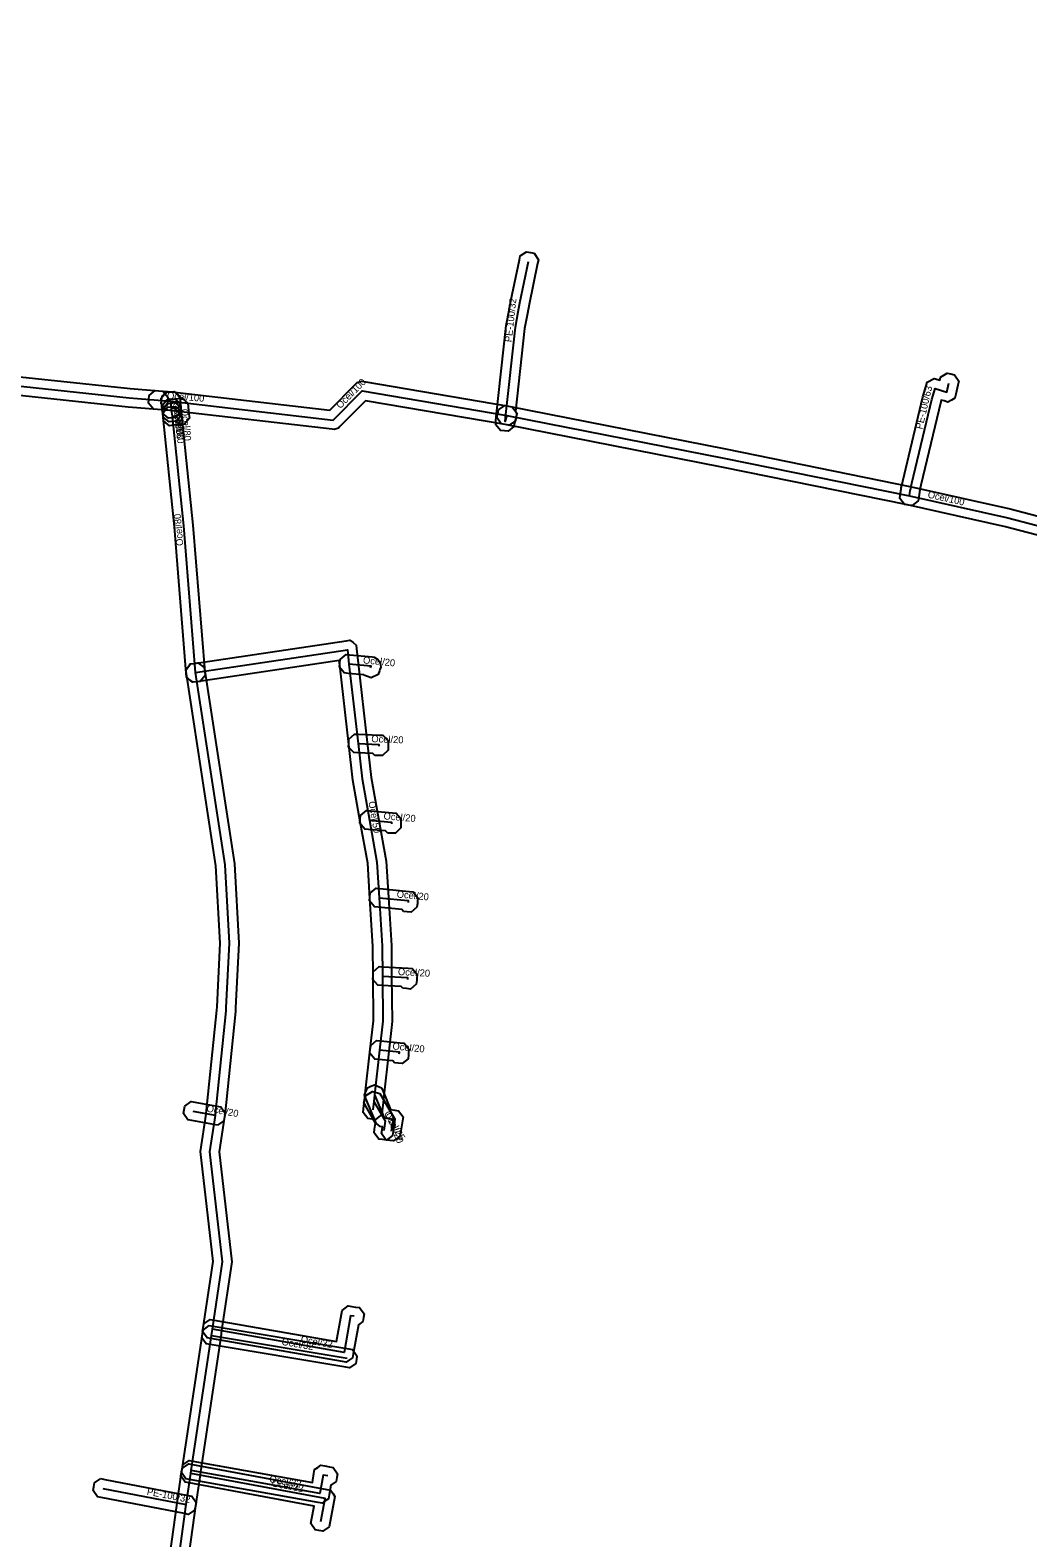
# Model space of a CAD drawing. Extents: x -569373 to -565022, y -1135090 to -1131496.
# Drawn here: x -566386.5 to -566279.2, y -1133844.4 to -1133682.3 of the extents above; entities that cross this region are included whole.
import ezdxf

# ---------------------------------------------------------------- set-up
doc = ezdxf.new("R2010")
doc.units = 0
for name, color, linetype in [('1', 7, 'Continuous'), ('24', 7, 'Continuous'), ('30', 7, 'Continuous')]:
    doc.layers.add(name, color=color, linetype=linetype)

msp = doc.modelspace()

# ---------------------------------------------------------------- linework, layer by layer
at = {"layer": '1'}
for points in [[(-566334.378, -1133724.484), (-566334.378, -1133724.487), (-566334.428, -1133724.884), (-566335.054, -1133725.391), (-566335.456, -1133725.356), (-566335.858, -1133725.322), (-566336.388, -1133724.715), (-566336.369, -1133724.312), (-566336.347, -1133723.861), (-566335.26, -1133714.052), (-566334.947, -1133712.384), (-566334.761, -1133711.396), (-566333.839, -1133706.966), (-566333.755, -1133706.56), (-566333.062, -1133706.107), (-566332.656, -1133706.191), (-566332.25, -1133706.275), (-566331.797, -1133706.968), (-566331.881, -1133707.374), (-566332.799, -1133711.784), (-566332.981, -1133712.754), (-566333.28, -1133714.348), (-566334.273, -1133723.294), (-566334.114, -1133723.584), (-566334.23, -1133723.981)], [(-566288.851, -1133719.853), (-566288.618, -1133719.923), (-566288.543, -1133719.595), (-566287.843, -1133719.153), (-566287.439, -1133719.245), (-566287.035, -1133719.337), (-566286.593, -1133720.037), (-566286.685, -1133720.441), (-566286.905, -1133721.411), (-566287.001, -1133721.835), (-566287.377, -1133722.054), (-566287.752, -1133722.273), (-566288.169, -1133722.147), (-566288.477, -1133722.055), (-566288.534, -1133722.242), (-566290.656, -1133731.215), (-566290.724, -1133731.52), (-566290.814, -1133731.918), (-566290.824, -1133731.961), (-566290.888, -1133732.474), (-566290.939, -1133732.885), (-566291.593, -1133733.393), (-566292.004, -1133733.342), (-566292.415, -1133733.291), (-566292.923, -1133732.637), (-566292.872, -1133732.226), (-566292.796, -1133731.619), (-566292.766, -1133731.482), (-566292.676, -1133731.08), (-566292.604, -1133730.765), (-566290.466, -1133721.718), (-566290.096, -1133720.516), (-566289.974, -1133720.121), (-566289.246, -1133719.734)], [(-566371.626, -1133721.129), (-566371.215, -1133721.177), (-566354.229, -1133723.15), (-566351.462, -1133720.347), (-566351.29, -1133720.173), (-566350.824, -1133720.023), (-566350.582, -1133720.064), (-566335.022, -1133722.714), (-566334.614, -1133722.784), (-566334.134, -1133723.46), (-566334.204, -1133723.868), (-566334.274, -1133724.276), (-566334.95, -1133724.756), (-566335.358, -1133724.686), (-566350.404, -1133722.123), (-566353.148, -1133724.903), (-566353.31, -1133725.067), (-566353.746, -1133725.22), (-566353.975, -1133725.193), (-566371.445, -1133723.163), (-566371.857, -1133723.115), (-566372.371, -1133722.466), (-566372.323, -1133722.055), (-566372.275, -1133721.643)], [(-566373.022, -1133721.03), (-566372.609, -1133721.063), (-566371.249, -1133721.173), (-566370.836, -1133721.207), (-566370.3, -1133721.838), (-566370.333, -1133722.251), (-566370.367, -1133722.664), (-566370.998, -1133723.2), (-566371.411, -1133723.167), (-566372.771, -1133723.057), (-566373.184, -1133723.023), (-566373.72, -1133722.392), (-566373.687, -1133721.979), (-566373.653, -1133721.566)], [(-566372.204, -1133723.482), (-566372.245, -1133723.07), (-566372.325, -1133722.27), (-566372.366, -1133721.857), (-566371.842, -1133721.216), (-566371.43, -1133721.175), (-566371.017, -1133721.134), (-566370.376, -1133721.658), (-566370.335, -1133722.07), (-566370.255, -1133722.87), (-566370.214, -1133723.283), (-566370.738, -1133723.924), (-566371.15, -1133723.965), (-566371.563, -1133724.006)], [(-566372.153, -1133723.894), (-566372.199, -1133723.482), (-566372.244, -1133723.082), (-566372.29, -1133722.67), (-566371.774, -1133722.022), (-566371.362, -1133721.976), (-566370.95, -1133721.93), (-566370.302, -1133722.446), (-566370.256, -1133722.858), (-566370.211, -1133723.258), (-566370.165, -1133723.67), (-566370.681, -1133724.318), (-566371.093, -1133724.364), (-566371.505, -1133724.41)], [(-566372.154, -1133723.883), (-566372.2, -1133723.484), (-566372.205, -1133723.48), (-566372.245, -1133723.068), (-566372.286, -1133722.655), (-566371.76, -1133722.015), (-566371.348, -1133721.975), (-566370.84, -1133721.925), (-566370.553, -1133721.895), (-566370.14, -1133721.853), (-566369.819, -1133722.115), (-566369.497, -1133722.377), (-566369.455, -1133722.789), (-566369.375, -1133723.579), (-566369.334, -1133723.988), (-566369.849, -1133724.627), (-566370.257, -1133724.674), (-566371.047, -1133724.764), (-566371.458, -1133724.811), (-566372.107, -1133724.295)], [(-566372.108, -1133724.294), (-566372.154, -1133723.882), (-566372.199, -1133723.482), (-566372.245, -1133723.07), (-566371.729, -1133722.422), (-566371.317, -1133722.376), (-566370.905, -1133722.33), (-566370.257, -1133722.846), (-566370.211, -1133723.258), (-566370.166, -1133723.658), (-566370.12, -1133724.07), (-566370.636, -1133724.718), (-566371.048, -1133724.764), (-566371.46, -1133724.81)], [(-566369.633, -1133751.843), (-566369.667, -1133751.43), (-566370.936, -1133735.682), (-566372.155, -1133723.873), (-566372.197, -1133723.461), (-566371.675, -1133722.818), (-566371.263, -1133722.775), (-566370.851, -1133722.733), (-566370.208, -1133723.255), (-566370.165, -1133723.667), (-566368.944, -1133735.498), (-566367.673, -1133751.27), (-566367.64, -1133751.683), (-566368.177, -1133752.313), (-566368.59, -1133752.347), (-566369.003, -1133752.38)], [(-566335.403, -1133722.639), (-566334.997, -1133722.719), (-566311.664, -1133727.309), (-566291.671, -1133731.372), (-566281.074, -1133733.748), (-566267.252, -1133737.363), (-566262.727, -1133738.207), (-566245.247, -1133741.457), (-566244.84, -1133741.533), (-566244.371, -1133742.216), (-566244.447, -1133742.623), (-566244.523, -1133743.03), (-566245.206, -1133743.499), (-566245.613, -1133743.423), (-566263.093, -1133740.173), (-566267.688, -1133739.317), (-566281.546, -1133735.692), (-566292.089, -1133733.328), (-566312.056, -1133729.271), (-566335.383, -1133724.681), (-566335.789, -1133724.601), (-566336.251, -1133723.913), (-566336.171, -1133723.507), (-566336.091, -1133723.101)], [(-566369.227, -1133750.422), (-566368.817, -1133750.361), (-566352.487, -1133747.931), (-566352.067, -1133747.868), (-566351.73, -1133748.127), (-566351.393, -1133748.387), (-566351.346, -1133748.809), (-566351.176, -1133750.327), (-566350.196, -1133758.866), (-566349.77, -1133762.616), (-566348.986, -1133767.045), (-566348.165, -1133771.622), (-566347.932, -1133775.519), (-566347.61, -1133780.704), (-566347.58, -1133783.98), (-566347.529, -1133788.881), (-566347.886, -1133792.062), (-566348.426, -1133796.872), (-566348.506, -1133797.582), (-566348.606, -1133798.472), (-566348.652, -1133798.883), (-566349.3, -1133799.4), (-566349.712, -1133799.354), (-566350.123, -1133799.308), (-566350.64, -1133798.66), (-566350.594, -1133798.248), (-566350.494, -1133797.358), (-566350.414, -1133796.648), (-566349.874, -1133791.838), (-566349.531, -1133788.779), (-566349.58, -1133784), (-566349.61, -1133780.776), (-566349.928, -1133775.641), (-566350.155, -1133771.858), (-566350.954, -1133767.395), (-566351.75, -1133762.904), (-566352.184, -1133759.094), (-566353.164, -1133750.553), (-566353.219, -1133750.062), (-566368.523, -1133752.339), (-566368.933, -1133752.4), (-566369.598, -1133751.907), (-566369.659, -1133751.497), (-566369.72, -1133751.087)], [(-566350.564, -1133751.645), (-566350.587, -1133751.597), (-566352.266, -1133751.435), (-566352.678, -1133751.396), (-566353.205, -1133750.757), (-566353.165, -1133750.344), (-566353.126, -1133749.932), (-566352.487, -1133749.405), (-566352.074, -1133749.445), (-566349.684, -1133749.675), (-566349.454, -1133749.697), (-566349.061, -1133749.937), (-566348.937, -1133750.132), (-566348.813, -1133750.327), (-566348.76, -1133750.785), (-566348.837, -1133751.003), (-566348.897, -1133751.173), (-566349.035, -1133751.564), (-566349.782, -1133751.921), (-566350.173, -1133751.783)], [(-566349.374, -1133760.27), (-566349.599, -1133760.045), (-566351.23, -1133759.979), (-566351.644, -1133759.962), (-566352.206, -1133759.354), (-566352.189, -1133758.94), (-566352.172, -1133758.526), (-566351.564, -1133757.964), (-566351.15, -1133757.981), (-566348.92, -1133758.071), (-566348.518, -1133758.087), (-566347.96, -1133758.668), (-566347.96, -1133759.07), (-566347.96, -1133759.27), (-566347.96, -1133759.684), (-566348.546, -1133760.27), (-566348.96, -1133760.27)], [(-566347.994, -1133768.62), (-566348.246, -1133768.368), (-566350.053, -1133768.217), (-566350.466, -1133768.182), (-566351.001, -1133767.55), (-566350.967, -1133767.137), (-566350.932, -1133766.724), (-566350.3, -1133766.189), (-566349.887, -1133766.223), (-566347.497, -1133766.423), (-566347.108, -1133766.456), (-566346.58, -1133767.03), (-566346.58, -1133767.42), (-566346.58, -1133767.62), (-566346.58, -1133768.034), (-566347.166, -1133768.62), (-566347.58, -1133768.62)], [(-566346.322, -1133777.024), (-566346.498, -1133776.809), (-566349.022, -1133776.576), (-566349.435, -1133776.538), (-566349.964, -1133775.901), (-566349.926, -1133775.488), (-566349.888, -1133775.075), (-566349.251, -1133774.546), (-566348.838, -1133774.584), (-566345.698, -1133774.874), (-566345.283, -1133774.913), (-566345.018, -1133775.234), (-566344.754, -1133775.555), (-566344.795, -1133775.97), (-566344.815, -1133776.17), (-566344.856, -1133776.582), (-566345.497, -1133777.106), (-566345.91, -1133777.065)], [(-566346.392, -1133785.294), (-566346.548, -1133785.103), (-566348.635, -1133784.988), (-566349.049, -1133784.965), (-566349.601, -1133784.348), (-566349.578, -1133783.935), (-566349.555, -1133783.521), (-566348.938, -1133782.969), (-566348.525, -1133782.992), (-566345.805, -1133783.142), (-566345.378, -1133783.165), (-566345.1, -1133783.49), (-566344.822, -1133783.814), (-566344.865, -1133784.24), (-566344.885, -1133784.44), (-566344.926, -1133784.852), (-566345.567, -1133785.376), (-566345.98, -1133785.335)], [(-566347.282, -1133793.314), (-566347.461, -1133793.095), (-566348.978, -1133792.945), (-566349.39, -1133792.904), (-566349.916, -1133792.264), (-566349.875, -1133791.852), (-566349.834, -1133791.44), (-566349.194, -1133790.914), (-566348.782, -1133790.955), (-566346.652, -1133791.165), (-566346.239, -1133791.206), (-566345.976, -1133791.526), (-566345.714, -1133791.847), (-566345.755, -1133792.26), (-566345.775, -1133792.46), (-566345.816, -1133792.872), (-566346.457, -1133793.396), (-566346.87, -1133793.355)], [(-566348.842, -1133796.611), (-566348.634, -1133796.969), (-566347.242, -1133799.378), (-566347.43, -1133800.71), (-566347.488, -1133801.12), (-566348.15, -1133801.618), (-566348.56, -1133801.56), (-566348.97, -1133801.502), (-566349.468, -1133800.84), (-566349.41, -1133800.43), (-566349.318, -1133799.782), (-566350.366, -1133797.971), (-566350.573, -1133797.612), (-566350.359, -1133796.812), (-566350.001, -1133796.604), (-566349.642, -1133796.397)], [(-566348.655, -1133795.994), (-566348.496, -1133796.377), (-566347.69, -1133798.322), (-566347.25, -1133798.393), (-566346.841, -1133798.459), (-566346.598, -1133798.796), (-566346.356, -1133799.132), (-566346.423, -1133799.542), (-566346.633, -1133800.822), (-566346.7, -1133801.231), (-566347.373, -1133801.714), (-566347.782, -1133801.647), (-566348.191, -1133801.58), (-566348.674, -1133800.907), (-566348.607, -1133800.498), (-566348.559, -1133800.207), (-566348.56, -1133800.207), (-566348.816, -1133800.166), (-566349.224, -1133799.843), (-566349.324, -1133799.603), (-566350.344, -1133797.143), (-566350.503, -1133796.76), (-566350.186, -1133795.995), (-566349.803, -1133795.836), (-566349.42, -1133795.677)], [(-566366.306, -1133800.017), (-566366.714, -1133799.945), (-566369.084, -1133799.525), (-566369.492, -1133799.453), (-566369.967, -1133798.774), (-566369.895, -1133798.366), (-566369.823, -1133797.958), (-566369.144, -1133797.483), (-566368.736, -1133797.555), (-566366.366, -1133797.975), (-566365.958, -1133798.047), (-566365.483, -1133798.726), (-566365.555, -1133799.134), (-566365.627, -1133799.542)], [(-566350.672, -1133821.118), (-566351.155, -1133821.475), (-566351.705, -1133824.613), (-566351.776, -1133825.021), (-566352.116, -1133825.259), (-566352.455, -1133825.497), (-566352.863, -1133825.425), (-566367.023, -1133822.935), (-566367.431, -1133822.863), (-566367.907, -1133822.185), (-566367.835, -1133821.777), (-566367.763, -1133821.369), (-566367.085, -1133820.893), (-566366.677, -1133820.965), (-566353.502, -1133823.282), (-566352.985, -1133820.327), (-566352.915, -1133819.926), (-566352.255, -1133819.451), (-566351.852, -1133819.511), (-566351.452, -1133819.571), (-566351.042, -1133819.632), (-566350.55, -1133820.298), (-566350.611, -1133820.708)], [(-566367.194, -1133821.566), (-566366.786, -1133821.634), (-566352.196, -1133824.064), (-566351.787, -1133824.132), (-566351.306, -1133824.806), (-566351.374, -1133825.214), (-566351.442, -1133825.623), (-566352.116, -1133826.104), (-566352.524, -1133826.036), (-566367.114, -1133823.606), (-566367.523, -1133823.538), (-566368.004, -1133822.864), (-566367.936, -1133822.456), (-566367.868, -1133822.047)], [(-566356.27, -1133842.839), (-566356.192, -1133842.432), (-566355.911, -1133840.96), (-566369.362, -1133838.463), (-566369.77, -1133838.388), (-566370.239, -1133837.705), (-566370.163, -1133837.298), (-566370.088, -1133836.89), (-566369.405, -1133836.421), (-566368.998, -1133836.497), (-566354.558, -1133839.177), (-566354.149, -1133839.253), (-566353.914, -1133839.596), (-566353.68, -1133839.939), (-566353.758, -1133840.348), (-566354.228, -1133842.808), (-566354.305, -1133843.215), (-566354.991, -1133843.68), (-566355.398, -1133843.602), (-566355.805, -1133843.525)], [(-566353.551, -1133838.308), (-566354.125, -1133838.704), (-566354.315, -1133839.775), (-566354.388, -1133840.183), (-566354.728, -1133840.42), (-566355.068, -1133840.657), (-566355.476, -1133840.584), (-566369.306, -1133838.114), (-566369.714, -1133838.042), (-566370.187, -1133837.362), (-566370.114, -1133836.954), (-566370.042, -1133836.546), (-566369.362, -1133836.073), (-566368.954, -1133836.146), (-566356.109, -1133838.44), (-566355.935, -1133837.455), (-566355.862, -1133837.046), (-566355.52, -1133836.808), (-566355.178, -1133836.571), (-566354.769, -1133836.646), (-566354.279, -1133836.736), (-566353.872, -1133836.811), (-566353.401, -1133837.493), (-566353.476, -1133837.901)], [(-566378.848, -1133838.02), (-566378.441, -1133838.098), (-566369.481, -1133839.818), (-566369.074, -1133839.896), (-566368.61, -1133840.582), (-566368.688, -1133840.989), (-566368.766, -1133841.396), (-566369.452, -1133841.86), (-566369.859, -1133841.782), (-566378.819, -1133840.062), (-566379.226, -1133839.984), (-566379.69, -1133839.298), (-566379.612, -1133838.891), (-566379.534, -1133838.484)]]:
    msp.add_lwpolyline(points, close=True, dxfattribs=at)
for points in [[(-566396.09, -1133718.644), (-566375.718, -1133720.824), (-566374.824, -1133720.893), (-566372.613, -1133721.063), (-566372.2, -1133721.095), (-566371.661, -1133721.724), (-566371.693, -1133722.137), (-566371.725, -1133722.55), (-566372.354, -1133723.089), (-566372.767, -1133723.057), (-566374.978, -1133722.887), (-566375.902, -1133722.816), (-566396.27, -1133720.636)], [(-566372.717, -1133855.594), (-566370.66, -1133840.659), (-566370.17, -1133837.336), (-566370.119, -1133836.985), (-566367.939, -1133822.472), (-566367.839, -1133821.803), (-566366.779, -1133814.683), (-566368.139, -1133802.852), (-566367.532, -1133798.83), (-566367.524, -1133798.764), (-566366.378, -1133787.635), (-566366.362, -1133787.304), (-566366.031, -1133780.433), (-566366.486, -1133772.124), (-566369.658, -1133751.502), (-566369.721, -1133751.093), (-566369.231, -1133750.425), (-566368.822, -1133750.362), (-566368.413, -1133750.299), (-566367.745, -1133750.789), (-566367.682, -1133751.198), (-566364.494, -1133771.916), (-566364.029, -1133780.427), (-566364.364, -1133787.4), (-566364.382, -1133787.785), (-566365.536, -1133798.976), (-566365.548, -1133799.09), (-566366.121, -1133802.888), (-566364.761, -1133814.717), (-566365.861, -1133822.097), (-566365.961, -1133822.768), (-566368.141, -1133837.275), (-566368.19, -1133837.624), (-566368.68, -1133840.941), (-566370.743, -1133855.926)]]:
    msp.add_lwpolyline(points, dxfattribs=at)
at = {"layer": '24'}
for points in [[(-566655.56, -1133682.28), (-566611.27, -1133691.4), (-566563.79, -1133701.13), (-566514.74, -1133710.21), (-566508.02, -1133711.52), (-566449.74, -1133715.73), (-566419.47, -1133717.94), (-566396.18, -1133719.64), (-566375.81, -1133721.82), (-566374.901, -1133721.89), (-566372.69, -1133722.06)], [(-566335.19, -1133723.7), (-566335.36, -1133724.28), (-566335.37, -1133724.36), (-566335.35, -1133723.94), (-566334.27, -1133714.2), (-566333.964, -1133712.569), (-566333.78, -1133711.59), (-566332.86, -1133707.17)], [(-566291.88, -1133732.35), (-566291.81, -1133731.79), (-566291.79, -1133731.7), (-566291.7, -1133731.3), (-566291.63, -1133730.99), (-566289.5, -1133721.98), (-566289.14, -1133720.81), (-566287.88, -1133721.19), (-566287.66, -1133720.22)], [(-566372.69, -1133722.06), (-566371.33, -1133722.17)], [(-566371.33, -1133722.17), (-566353.86, -1133724.2), (-566350.75, -1133721.05), (-566335.19, -1133723.7)], [(-566371.25, -1133722.97), (-566371.33, -1133722.17)], [(-566371.16, -1133723.77), (-566370.37, -1133723.68), (-566370.45, -1133722.89), (-566370.74, -1133722.92), (-566371.25, -1133722.97)], [(-566371.205, -1133723.37), (-566371.25, -1133722.97)], [(-566371.16, -1133723.77), (-566371.205, -1133723.37)], [(-566368.67, -1133751.35), (-566369.94, -1133735.59), (-566371.16, -1133723.77)], [(-566335.19, -1133723.7), (-566311.86, -1133728.29), (-566291.88, -1133732.35), (-566281.31, -1133734.72), (-566267.47, -1133738.34), (-566262.91, -1133739.19), (-566245.43, -1133742.44)], [(-566368.67, -1133751.35), (-566352.34, -1133748.92), (-566352.17, -1133750.44), (-566351.19, -1133758.98), (-566350.76, -1133762.76), (-566349.97, -1133767.22), (-566349.16, -1133771.74), (-566348.93, -1133775.58), (-566348.61, -1133780.74), (-566348.58, -1133783.99), (-566348.53, -1133788.83), (-566348.88, -1133791.95), (-566349.42, -1133796.76), (-566349.5, -1133797.47), (-566349.6, -1133798.36)], [(-566371.73, -1133855.76), (-566369.67, -1133840.8), (-566369.18, -1133837.48), (-566369.13, -1133837.13), (-566366.95, -1133822.62), (-566366.85, -1133821.95), (-566365.77, -1133814.7), (-566367.13, -1133802.87), (-566366.54, -1133798.96), (-566366.53, -1133798.87), (-566365.38, -1133787.71), (-566365.363, -1133787.352), (-566365.03, -1133780.43), (-566365.49, -1133772.02), (-566368.67, -1133751.35)], [(-566349.84, -1133750.84), (-566349.78, -1133750.67), (-566352.17, -1133750.44)], [(-566351.19, -1133758.98), (-566348.96, -1133759.07), (-566348.96, -1133759.27)], [(-566349.97, -1133767.22), (-566347.58, -1133767.42), (-566347.58, -1133767.62)], [(-566348.93, -1133775.58), (-566345.79, -1133775.87), (-566345.81, -1133776.07)], [(-566348.58, -1133783.99), (-566345.86, -1133784.14), (-566345.88, -1133784.34)], [(-566346.77, -1133792.36), (-566346.75, -1133792.16), (-566348.88, -1133791.95)], [(-566349.42, -1133796.76), (-566348.4, -1133799.22), (-566347.41, -1133799.38), (-566347.62, -1133800.66)], [(-566366.54, -1133798.96), (-566368.91, -1133798.54)], [(-566349.5, -1133797.47), (-566348.28, -1133799.58), (-566348.42, -1133800.57)], [(-566351.6, -1133820.56), (-566352, -1133820.5), (-566352.69, -1133824.44), (-566366.85, -1133821.95)], [(-566366.95, -1133822.62), (-566352.36, -1133825.05)], [(-566355.21, -1133842.62), (-566354.74, -1133840.16), (-566369.18, -1133837.48)], [(-566354.46, -1133837.72), (-566354.95, -1133837.63), (-566355.3, -1133839.6), (-566369.13, -1133837.13)], [(-566378.63, -1133839.08), (-566369.67, -1133840.8)]]:
    msp.add_lwpolyline(points, dxfattribs=at)

# ---------------------------------------------------------------- texts
at = {"layer": '30'}
for s, rotation, p in [('PE-100/32', 83.67272, (-566334.676, -1133715.856)), ('Ocel/100', 45.3661, (-566353.103, -1133723.031)), ('PE-100/63', 76.69924, (-566290.518, -1133725.239)), ('Ocel/100', 355.37585, (-566371.76, -1133721.919)), ('Ocel/80', 275.71059, (-566371.095, -1133722.32)), ('Ocel/80', 276.41879, (-566371.033, -1133722.92)), ('Ocel/80', 276.41879, (-566370.988, -1133723.32)), ('Ocel/80', 275.78239, (-566370.215, -1133723.031)), ('Ocel/100', 347.36219, (-566289.977, -1133732.532)), ('Ocel/80', 94.60715, (-566369.986, -1133737.698)), ('Ocel/20', 354.50311, (-566350.685, -1133750.364)), ('Ocel/20', 357.68887, (-566349.775, -1133758.829)), ('Ocel/50', 280.04462, (-566350.082, -1133765.257)), ('Ocel/20', 355.21652, (-566348.475, -1133767.128)), ('Ocel/20', 354.72332, (-566347.06, -1133775.534)), ('Ocel/20', 356.8435, (-566346.92, -1133783.871)), ('Ocel/20', 354.36932, (-566347.515, -1133791.865)), ('Ocel/20', 349.95065, (-566367.525, -1133798.55)), ('Ocel/25', 300.03646, (-566348.44, -1133798.758)), ('Ocel/20', 292.52057, (-566348.27, -1133798.852)), ('Ocel/32', 350.54405, (-566359.455, -1133823.635)), ('Ocel/32', 350.02665, (-566357.401, -1133823.376)), ('PE-100/32', 349.13345, (-566373.95, -1133839.74)), ('Ocel/32', 349.87389, (-566360.785, -1133838.385)), ('Ocel/32', 349.48579, (-566360.529, -1133838.849))]:
    msp.add_text(s, height=0.75, rotation=rotation, dxfattribs=at).set_placement(p)

doc.saveas('drawing.dxf')
